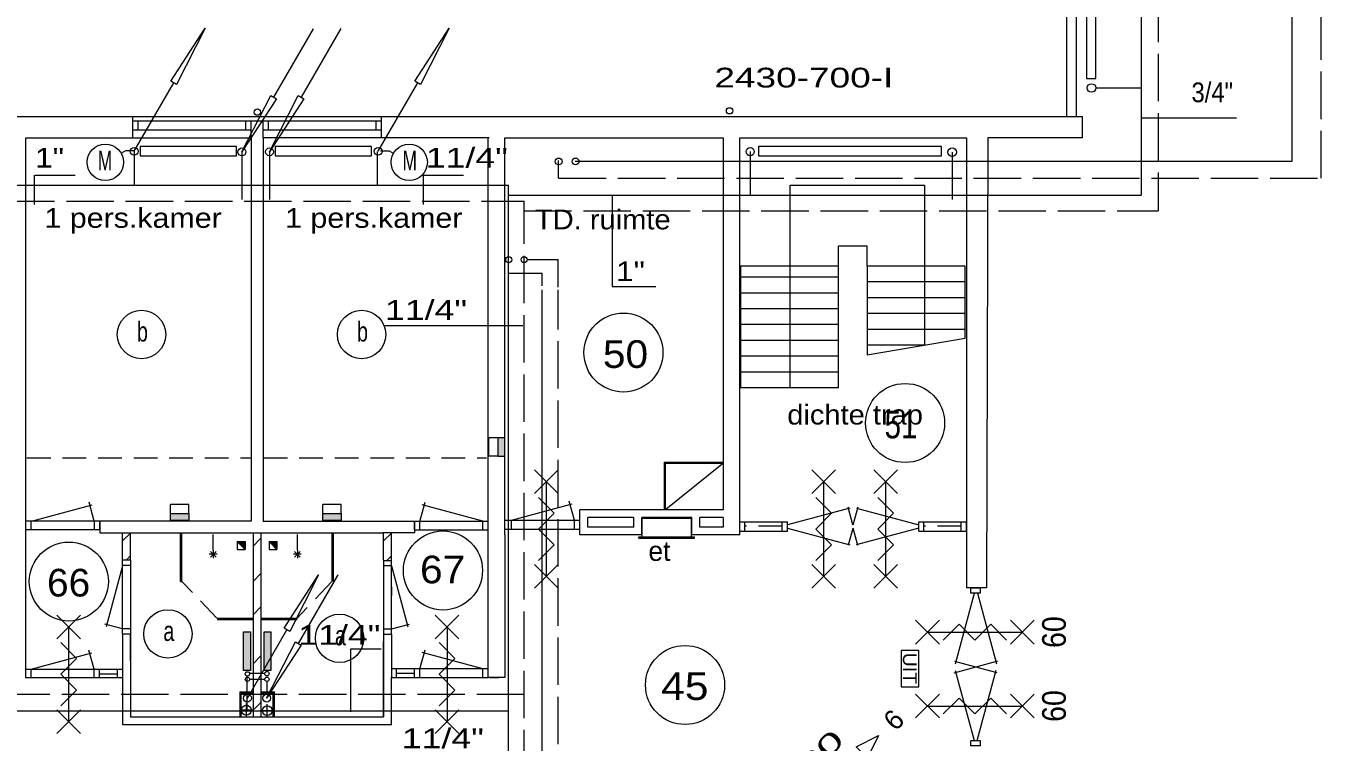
# Model space of a CAD drawing. Extents: x 295824 to 414724, y 24924 to 109024.
# Drawn here: x 320090 to 336476, y 39611 to 48675 of the extents above; entities that cross this region are included whole.
import ezdxf
from ezdxf.enums import TextEntityAlignment as Align

# ---------------------------------------------------------------- set-up
doc = ezdxf.new("R2010")
doc.units = 0
doc.header["$LTSCALE"] = 100
for name, pattern in [('DOT_DASHED', [7.7, 5, -1.2, 0.3, -1.2]), ('LONG_DASHED', [7.5, 6, -1.5]), ('MEDIUM_DASHED', [4.5, 3, -1.5])]:
    doc.linetypes.add(name, pattern=pattern)
doc.layers.add('16', color=7, linetype='Continuous', lineweight=13)
doc.layers.add('61', color=7, linetype='Continuous', lineweight=13)

msp = doc.modelspace()

# ---------------------------------------------------------------- hatches: boundary and pattern name
at = {"layer": '16'}
for points in [[(326148.9, 43232), (326148.9, 43463.5), (326062.4, 43463.5), (326062.4, 43232)], [(322152.7, 42415.9), (321921.2, 42415.9), (321921.2, 42502.4), (322152.7, 42502.4)], [(324077.6, 42415.9), (323846.1, 42415.9), (323846.1, 42502.4), (324077.6, 42502.4)], [(322843.9, 41008.8), (322929.4, 41008.8), (322929.4, 40516.6), (322843.9, 40516.6)], [(323103.1, 41008.8), (323188.5, 41008.8), (323188.5, 40516.6), (323103.1, 40516.6)]]:
    msp.add_hatch(color=256, dxfattribs=at).paths.add_polyline_path(points)
at = {"layer": '61'}
for points in [[(322863, 42048.6), (322763, 42148.6), (322863, 42148.6)], [(323266, 42048.6), (323166, 42148.6), (323266, 42148.6)]]:
    msp.add_hatch(color=256, dxfattribs=at).paths.add_polyline_path(points)

# ---------------------------------------------------------------- linework, layer by layer
at = {"layer": '16', "linetype": 'LONG_DASHED'}
for p, q in [((336475.7, 46746.4), (336475.7, 56755.7)), ((334414.3, 53571.2), (334414.3, 46333)), ((322820.3, 47078.4), (322820.3, 46458)), ((323173.8, 47078.1), (323173.8, 46458)), ((331809.5, 47078.1), (331809.5, 46333)), ((326829.9, 46746.4), (326829.9, 46969.9)), ((326829.9, 46746.4), (336475.7, 46746.4)), ((304851.7, 46458), (326394, 46458)), ((326394, 31665.3), (326394, 46458)), ((326394, 46333), (334414.3, 46333)), ((326435.5, 45718.9), (326822.5, 45718.9)), ((326822.5, 45368.8), (326822.5, 45718.9)), ((326822.5, 34334.7), (326822.5, 45336.6)), ((322919.9, 40407.1), (323111.4, 40407.1)), ((323142.4, 40217.7), (323142.4, 40381.3)), ((326394, 40214.6), (302769.9, 40214.6))]:
    msp.add_line(p, q, dxfattribs=at)
at = {"layer": '16'}
for p, q in [((336108.4, 46961.7), (336108.4, 56593.1)), ((334199, 51029.1), (334199, 46533)), ((323723, 48638.8), (323223, 47772.8)), ((324072.1, 48640.7), (323572.1, 47774.7)), ((321459.4, 47087.9), (321959.4, 47953.9)), ((324546.2, 47087.9), (325046.2, 47953.9)), ((333624, 47889.7), (334199, 47889.7)), ((334210.6, 47511.7), (335404.4, 47511.7)), ((321459.6, 47084.6), (321459.6, 46658)), ((324535.8, 47084.6), (324535.8, 46658)), ((329253.1, 47084.3), (329253.1, 46533)), ((327039.2, 46961.7), (336108.4, 46961.7)), ((320200.7, 46416.7), (320200.7, 46784.2)), ((320206.6, 46784.2), (320711.7, 46784.2)), ((303410.7, 46658), (326194, 46658)), ((309466.3, 46658), (325376.7, 46658)), ((326194, 31465.3), (326194, 46658)), ((326197.5, 46533), (334199, 46533)), ((326198.1, 45548.1), (326622.5, 45548.1)), ((326622.5, 45385.4), (326622.5, 45548.1)), ((326622.5, 34365.3), (326622.5, 45336.7)), ((326374.7, 44877.7), (324629.9, 44877.7)), ((326062.4, 43463.5), (325948.5, 43463.5)), ((321921.2, 42502.4), (321921.2, 42616.3)), ((323846.1, 42502.4), (323846.1, 42616.3)), ((324035.7, 41726.5), (323535.7, 40860.5)), ((322892.7, 40168.1), (323392.7, 41034.1)), ((323111.5, 40477.8), (322919.8, 40477.8)), ((322891.2, 40002.8), (322891.2, 40442.4)), ((326194, 40002.8), (302570.9, 40002.8))]:
    msp.add_line(p, q, dxfattribs=at)
for points in [[(333507, 50325.3), (333507, 48010.2), (333624.9, 48010.2), (333624.9, 50325.3)], [(322359.4, 48646.9), (321995.4, 47932.9), (321923.4, 47974.9)], [(325446.2, 48646.9), (325082.2, 47932.9), (325010.2, 47974.9)], [(322823, 47079.8), (323187, 47793.8), (323259, 47751.8)], [(323172.1, 47081.7), (323536.1, 47795.7), (323608.1, 47753.7)], [(321536.2, 47031.2), (322755.5, 47031.2), (322755.5, 47149.1), (321536.2, 47149.1)], [(323244.5, 47031.2), (324463.8, 47031.2), (324463.8, 47149.1), (323244.5, 47149.1)], [(329358.9, 47031.2), (331674, 47031.2), (331674, 47149.1), (329358.9, 47149.1)], [(326148.9, 43232), (326148.9, 43463.5), (326062.4, 43463.5), (326062.4, 43232)], [(322152.7, 42415.9), (321921.2, 42415.9), (321921.2, 42502.4), (322152.7, 42502.4)], [(324077.6, 42415.9), (323846.1, 42415.9), (323846.1, 42502.4), (324077.6, 42502.4)], [(323792.7, 41727.1), (323428.7, 41013.1), (323356.7, 41055.1)], [(322843.9, 41008.8), (322929.4, 41008.8), (322929.4, 40516.6), (322843.9, 40516.6)], [(323103.1, 41008.8), (323188.5, 41008.8), (323188.5, 40516.6), (323103.1, 40516.6)], [(323135.7, 40167.5), (323499.7, 40881.5), (323571.7, 40839.5)]]:
    msp.add_lwpolyline(points, close=True, dxfattribs=at)
for points in [[(321455.8, 47094.6), (321349.8, 47094.6), (321290.3, 47060.2)], [(324577.9, 47094.6), (324683.9, 47094.6), (324743.4, 47060.2)], [(325119.7, 46416.7), (325119.7, 46784.2), (325624.7, 46784.2)], [(327507.2, 46523.9), (327507.2, 45375.4), (328058.2, 45375.4)], [(326062.4, 43232), (325948.5, 43232), (325948.5, 43463.5)], [(322152.7, 42502.4), (322152.7, 42616.3), (321921.2, 42616.3)], [(324077.6, 42502.4), (324077.6, 42616.3), (323846.1, 42616.3)], [(324201.4, 39996.4), (324201.4, 40792.7), (324584, 40792.7)]]:
    msp.add_lwpolyline(points, dxfattribs=at)
for centre, radius in [((333569.6, 47889.7), 54.4), ((321094.7, 46949.2), 229.9), ((321459.4, 47087.6), 50), ((322823, 47080.2), 50), ((323172.1, 47082), 50), ((324546.2, 47087.6), 50), ((324939, 46949.2), 229.9), ((329253.1, 47084.3), 51.4), ((331809.5, 47078.1), 54.4), ((326829.9, 46960.4), 42.6), ((327044.2, 46960.4), 42.6), ((326197.9, 45716.6), 38), ((326393, 45716.6), 38), ((322892, 40474.8), 27.9), ((323139.4, 40477.8), 27.9), ((322892, 40407), 27.9), ((323139.4, 40407), 27.9), ((322892.7, 40167.8), 50), ((323135.7, 40167.8), 50)]:
    msp.add_circle(centre, radius, dxfattribs=at)
at = {"layer": '61'}
for p, q in [((333257, 47527.9), (333257, 54115.7)), ((333377, 54115.7), (333377, 47527.2)), ((301828.9, 47527.9), (333452, 47527.9)), ((313820.3, 47527.9), (333174.1, 47527.9)), ((321441.1, 47257.3), (321441.1, 47527.3)), ((324590.1, 47257.3), (324590.1, 47527.3)), ((333452, 47527.9), (333452, 47257.9)), ((321442, 47472.1), (322941, 47472.1)), ((321442, 47358.1), (321442, 47472.1)), ((321442, 47358.1), (322940, 47358.1)), ((321509, 47358.1), (321509, 47471.5)), ((322874, 47472.1), (324590, 47472.1)), ((322874, 47358.5), (322874, 47472.1)), ((322941, 47359.1), (322941, 47472.1)), ((322941.1, 47257.3), (322941.1, 47472.1)), ((323090.1, 47257.3), (323090.1, 47472.1)), ((323090.9, 47358.1), (323090.9, 47472.1)), ((323090.9, 47358.1), (324589, 47358.1)), ((323157.9, 47358.1), (323157.9, 47471.5)), ((324523, 47358.5), (324523, 47471.5)), ((324590, 47359.1), (324590, 47472.1)), ((320090.1, 47257.9), (322941.2, 47257.9)), ((320090.1, 40532.9), (320090.1, 47257.9)), ((320090.4, 47257.9), (322940.4, 47257.9)), ((320090.5, 47257.9), (322940.5, 47257.9)), ((322940.1, 47257.9), (322940.1, 42407.9)), ((325940.1, 47257.9), (323090.1, 47257.9)), ((325949, 47257.9), (323099, 47257.9)), ((325940.1, 40428.5), (325940.1, 47257.9)), ((328910.1, 47257.9), (328910.1, 42552.9)), ((332260.1, 47257.9), (332241.7, 41563.5)), ((333452, 47257.9), (332260.1, 47257.9)), ((330368.9, 45635), (330368.9, 45892.9)), ((330368.9, 45892.9), (330732.6, 45892.9)), ((330732.6, 45635), (330732.6, 45892.9)), ((331972.5, 45635), (330732.6, 45635)), ((331972.5, 44722.2), (331972.5, 45635)), ((329129, 45498.6), (330368.9, 45498.6)), ((331972.5, 45435), (330732.6, 45435)), ((329129, 45298.6), (330368.9, 45298.6)), ((331972.5, 45235), (330732.6, 45235)), ((329129, 45098.6), (330368.9, 45098.6)), ((329129, 44898.6), (330368.9, 44898.6)), ((331972.5, 45035), (330732.6, 45035)), ((331972.5, 44835), (330732.6, 44835)), ((329129, 44698.6), (330368.9, 44698.6)), ((330732.6, 44511), (331972.5, 44722.2)), ((331460.5, 44635), (330732.6, 44635)), ((329129, 44498.6), (330368.9, 44498.6)), ((329129, 44298.6), (330368.9, 44298.6)), ((329129, 44098.6), (330368.9, 44098.6)), ((328168.4, 43154.8), (328910.1, 43154.8)), ((328168.4, 42552.9), (328168.4, 43154.8)), ((328183.4, 43139.8), (328910.1, 43139.8)), ((328183.4, 42552.9), (328183.4, 43139.8)), ((328898.2, 43126.8), (328183.9, 42555.9)), ((326523.6, 42757.7), (326823.6, 43057.7)), ((326823.6, 42757.7), (326523.6, 43057.7)), ((330031.9, 42757.7), (330331.9, 43057.7)), ((330331.9, 42757.7), (330031.9, 43057.7)), ((330816, 42757.7), (331116, 43057.7)), ((331116, 42757.7), (330816, 43057.7)), ((326673.6, 42907.7), (326673.6, 41707.7)), ((330181.9, 42907.7), (330181.9, 41707.7)), ((330966, 42907.7), (330966, 41707.7)), ((320158.9, 42409.2), (320926.2, 42614.8)), ((320953.4, 42407.1), (320888.4, 42649.8)), ((325075.2, 42405.1), (325140.3, 42647.8)), ((325869.8, 42407.2), (325102.5, 42612.8)), ((326234.9, 42421.6), (327002.2, 42627.2)), ((327029.5, 42419.5), (326964.4, 42662.2)), ((327099.3, 42232.9), (327099.3, 42552.9)), ((328910.1, 42552.9), (327099.3, 42552.9)), ((327780.3, 42452.9), (327199.3, 42452.9)), ((327780.3, 42332.9), (327780.3, 42452.9)), ((327880.3, 42234.5), (327880.3, 42452.9)), ((328515.5, 42452.9), (327880.3, 42452.9)), ((327884.6, 42217.1), (327884.6, 42444.5)), ((327884.6, 42444.5), (328508.9, 42444.5)), ((328508.9, 42209.4), (328508.9, 42444.5)), ((328910.1, 42552.9), (328512.1, 42552.9)), ((328515.5, 42232.9), (328515.5, 42452.9)), ((328910.1, 42452.9), (328615.5, 42452.9)), ((328910.1, 42452.9), (328910.1, 42332.9)), ((330512, 42572.2), (329725.6, 42361.4)), ((330553, 42361.5), (330493.5, 42583.4)), ((330556, 42361.1), (330617.3, 42590)), ((330597.9, 42572.2), (331385.2, 42361.3)), ((321021.2, 42299.4), (320090.4, 42299.4)), ((320156.3, 42299.1), (320156.3, 42409.1)), ((322940.1, 42407.9), (320878.9, 42407.9)), ((320956.3, 42299.1), (320956.3, 42409.1)), ((321023.3, 42299.1), (321023.3, 42409.1)), ((323088.9, 42407.9), (325031.4, 42407.9)), ((323090.4, 42407.9), (325938.2, 42407.9)), ((325005.4, 42297.1), (325005.4, 42407.1)), ((325007.5, 42297.4), (325938.3, 42297.4)), ((325072.4, 42297.1), (325072.4, 42407.1)), ((325872.4, 42297.1), (325872.4, 42407.1)), ((325938.3, 42297.4), (325938.3, 42407.8)), ((326152.8, 42421), (327089.5, 42421)), ((326152.8, 42307.3), (327093.8, 42307.3)), ((326232.3, 42311.5), (326232.3, 42421.5)), ((327032.3, 42311.5), (327032.3, 42421.5)), ((329120, 42398.2), (329724.8, 42398.2)), ((329120, 42282), (329120, 42396)), ((329120.6, 42282), (329724.8, 42282)), ((329187, 42282.9), (329187, 42396.9)), ((329657.8, 42282.9), (329657.8, 42396.9)), ((329724.8, 42282), (329724.8, 42398.2)), ((329724.9, 42319), (330514.2, 42107.5)), ((330497.1, 42106.1), (330554, 42318.6)), ((330615.2, 42097.9), (330555.9, 42319.3)), ((331385, 42319.1), (330593.9, 42107.1)), ((331384.8, 42282), (331384.8, 42398.2)), ((331384.8, 42398.2), (331990, 42398.2)), ((331384.8, 42282), (331989.4, 42282)), ((331451.8, 42282.9), (331451.8, 42396.9)), ((331923, 42281.8), (331923, 42394.9)), ((331990, 42280.9), (331990, 42394.9)), ((321024.2, 42257.9), (324614.3, 42257.9)), ((321314, 41911.5), (321314, 42257.9)), ((321314, 42157.2), (321414.4, 42257.6)), ((321412.7, 41911.5), (321412.7, 42257.9)), ((322046.7, 41644.6), (322046.7, 42253)), ((322064.7, 41644.6), (322064.7, 42253)), ((322459.5, 42039.2), (322459.5, 42239.2)), ((322963.9, 42257.9), (322963.9, 39932.9)), ((322964.4, 42093), (323062.9, 42191.5)), ((323063.9, 42257.9), (323063.9, 39932.9)), ((323524, 42039.2), (323524, 42239.2)), ((323964.5, 41650.7), (323964.5, 42255.5)), ((323982.5, 41650.7), (323982.5, 42255.5)), ((324614.3, 41911.9), (324614.3, 42258.3)), ((324614.5, 42157.2), (324714.9, 42257.6)), ((324714.1, 41911.5), (324714.1, 42257.9)), ((327880.3, 42232.9), (327099.3, 42232.9)), ((327845.3, 42209.4), (328546.5, 42209.4)), ((327845.3, 42191.9), (327845.3, 42209.4)), ((327845.3, 42191.9), (328546.5, 42191.9)), ((329120.1, 42232.9), (328515.5, 42232.9)), ((328546.5, 42191.9), (328546.5, 42209.4)), ((321356.4, 41913.2), (321413, 41969.9)), ((322509.5, 41989.2), (322409.5, 41989.2)), ((322494.9, 42024.5), (322424.2, 41953.8)), ((322494.9, 41953.8), (322424.2, 42024.5)), ((322459.5, 42039.2), (322459.5, 41939.2)), ((323574, 41989.2), (323474, 41989.2)), ((323559.4, 42024.5), (323488.7, 41953.8)), ((323559.4, 41953.8), (323488.7, 42024.5)), ((323524, 42039.2), (323524, 41939.2)), ((324658.3, 41913.2), (324714.9, 41969.9)), ((321314, 41841.3), (321107.1, 41069.1)), ((321313.8, 40977.9), (321313.8, 41911.9)), ((321413.8, 41911.9), (321313.8, 41911.9)), ((321413.9, 41844.9), (321313.8, 41844.9)), ((321413.8, 41911.9), (321413.8, 40977.9)), ((324613.7, 41844.5), (324713.9, 41844.5)), ((324613.9, 41911.5), (324613.9, 40977.5)), ((324614.3, 41911.5), (324714.5, 41911.5)), ((324713.6, 41841), (324920.5, 41068.7)), ((324713.9, 40976.7), (324713.9, 41911.5)), ((326523.6, 41557.7), (326823.6, 41857.7)), ((326823.6, 41557.7), (326523.6, 41857.7)), ((330031.9, 41557.7), (330331.9, 41857.7)), ((330331.9, 41557.7), (330031.9, 41857.7)), ((330816, 41557.7), (331116, 41857.7)), ((331116, 41557.7), (330816, 41857.7)), ((322046.7, 41644.6), (322064.7, 41644.6)), ((322964.4, 41645.4), (323062.9, 41743.9)), ((323964.5, 41650.7), (323982.5, 41650.7)), ((324714, 41578.4), (324714, 41468)), ((331851.1, 40602.2), (332090.7, 41496.3)), ((332241.7, 41563.5), (331990.1, 41563.5)), ((332130.7, 41496.3), (332369.8, 40603.9)), ((322964.4, 41222.9), (323062.9, 41321.4)), ((320480.8, 40919.8), (320780.8, 41219.8)), ((320780.8, 40919.8), (320480.8, 41219.8)), ((322963.5, 41158.7), (322513.2, 41158.7)), ((323514.9, 41176.7), (323064.9, 41176.7)), ((323514.9, 41158.7), (323064.9, 41158.7)), ((323514.9, 41176.7), (323514.9, 41158.7)), ((325268.5, 40919.8), (325568.5, 41219.8)), ((325568.5, 40919.8), (325268.5, 41219.8)), ((331646.2, 40852.6), (331346.2, 41152.6)), ((331646.2, 41152.6), (331346.2, 40852.6)), ((332846.2, 40852.6), (332546.2, 41152.6)), ((332846.2, 41152.6), (332546.2, 40852.6)), ((320630.8, 41069.8), (320630.8, 39869.8)), ((321314, 41043.9), (321086.7, 41104.8)), ((321413.8, 40977.9), (321313.8, 40977.9)), ((321313.9, 40975.3), (321313.9, 40188.2)), ((321413.6, 41044.9), (321314.3, 41044.9)), ((321413.9, 40638.2), (321413.9, 40975.3)), ((324613.9, 40977.5), (324613.9, 39932.9)), ((324613.9, 40977.5), (324713.9, 40977.5)), ((324614, 41044.5), (324713.4, 41044.5)), ((324713.6, 41043.5), (324940.9, 41104.4)), ((324713.9, 40977.5), (324713.9, 40532.9)), ((325418.5, 41069.8), (325418.5, 39869.8)), ((331496.2, 41002.6), (332696.2, 41002.6)), ((320157.7, 40535.1), (320924.9, 40740.7)), ((320952.2, 40532.9), (320887.2, 40775.7)), ((322964.4, 40603), (323062.9, 40701.4)), ((325075.2, 40536.8), (325140.3, 40779.5)), ((325869.8, 40539), (325102.5, 40744.6)), ((320155.1, 40424.9), (320155.1, 40534.9)), ((320955.1, 40424.9), (320955.1, 40534.9)), ((321022.1, 40424.9), (321022.1, 40534.9)), ((321022.9, 40475.7), (321247.6, 40475.7)), ((321247.6, 40424.9), (321247.6, 40534.9)), ((324779.9, 40428.8), (324779.9, 40538.8)), ((325004.6, 40479.6), (324779.9, 40479.6)), ((325005.4, 40428.8), (325005.4, 40538.8)), ((325072.4, 40428.8), (325072.4, 40538.8)), ((325872.4, 40428.8), (325872.4, 40538.8)), ((332107.3, 40560.2), (331828.5, 40485.5)), ((332106.9, 40561.2), (331843.4, 40631.8)), ((331847.3, 40516.5), (332084.6, 39630.7)), ((332382.4, 40635.1), (332108.4, 40561.7)), ((332376.5, 40488.2), (332109.1, 40559.9)), ((332124.6, 39630.6), (332363.2, 40520.9)), ((325959.8, 40428.6), (326073.8, 40428.6)), ((322796.2, 40248), (322963.9, 40248)), ((322796.2, 40248), (322796.2, 39932.9)), ((322810.5, 40234.4), (322963.9, 40234.4)), ((322810.5, 40234.4), (322810.5, 39934)), ((323064, 40234.4), (323218.7, 40234.4)), ((323065, 40248), (323233.7, 40248)), ((323218.7, 39932.9), (323218.7, 40234.4)), ((323233.7, 39932.9), (323233.7, 40248)), ((331646.2, 39917.2), (331346.2, 40217.2)), ((331646.2, 40217.2), (331346.2, 39917.2)), ((332846.2, 39917.2), (332546.2, 40217.2)), ((332846.2, 40217.2), (332546.2, 39917.2)), ((320480.8, 39719.8), (320780.8, 40019.8)), ((320780.8, 39719.8), (320480.8, 40019.8)), ((322977.5, 40026.8), (323062.9, 40112.1)), ((325268.5, 39719.8), (325568.5, 40019.8)), ((325568.5, 39719.8), (325268.5, 40019.8)), ((331496.2, 40067.2), (332696.2, 40067.2))]:
    msp.add_line(p, q, dxfattribs=at)
at = {"layer": '61', "linetype": 'MEDIUM_DASHED'}
for p, q in [((320103.3, 43208.1), (322935.1, 43208.1)), ((323098.4, 43208.1), (325916.3, 43208.1)), ((329656.2, 42342.2), (329186.7, 42342.2)), ((331921.7, 42342.2), (331452.9, 42342.2)), ((322505.8, 41179.8), (322064, 41644.8)), ((323960.1, 41643.1), (323516.1, 41175.8))]:
    msp.add_line(p, q, dxfattribs=at)
at = {"layer": '61', "linetype": 'DOT_DASHED'}
for p, q in [((322968, 40015.2), (322804, 40015.2)), ((322879.5, 39934.8), (322879.5, 40098.9)), ((323227.8, 40007.7), (323063.7, 40007.7)), ((323142.7, 39933.5), (323142.7, 40092.8))]:
    msp.add_line(p, q, dxfattribs=at)
at = {"layer": '61'}
for points in [[(325940.4, 47257.9), (323090.4, 47257.9), (323090.4, 42407.9)], [(325940.5, 47257.9), (323090.5, 47257.9), (323090.5, 42407.9)], [(326150.1, 42234.5), (326150.1, 47257.9), (328910.1, 47257.9)], [(329120.1, 42232.9), (329120.1, 47257.9), (331990.1, 47257.9), (331990.1, 41563.5)], [(329757.2, 44098.6), (329757.2, 46659.3), (331460, 46659.3), (331460, 44634.9)], [(331972.5, 45635), (330732.6, 45635), (330732.6, 44511)], [(326573.6, 42707.7), (326773.6, 42507.7), (326573.6, 42307.7), (326773.6, 42107.7), (326573.6, 41907.7)], [(330081.9, 42707.7), (330281.9, 42507.7), (330081.9, 42307.7), (330281.9, 42107.7), (330081.9, 41907.7)], [(330866, 42707.7), (331066, 42507.7), (330866, 42307.7), (331066, 42107.7), (330866, 41907.7)], [(327780.3, 42332.9), (327199.3, 42332.9), (327199.3, 42452.9)], [(328910.1, 42332.9), (328615.5, 42332.9), (328615.5, 42452.9)], [(320090.4, 42299.4), (320090.4, 42409.8), (321023.7, 42409.8)], [(322938.9, 42407.9), (321024.2, 42407.9), (321024.2, 42257.9)], [(325005, 42407.8), (325005, 42257.9), (324599.6, 42257.9)], [(322763, 42148.6), (322863, 42148.6), (322863, 42048.6)], [(323166, 42148.6), (323266, 42148.6), (323266, 42048.6)], [(326150.1, 42232.9), (326150.1, 40428.5), (325940.1, 40428.5)], [(321413.9, 41158.7), (321413.9, 39932.9), (323293.9, 39932.9)], [(322963.5, 41176.7), (322513.2, 41176.7), (322513.2, 41158.7)], [(331696.2, 40902.6), (331896.2, 41102.6), (332096.2, 40902.6), (332296.2, 41102.6), (332496.2, 40902.6)], [(320530.8, 40869.8), (320730.8, 40669.8), (320530.8, 40469.8), (320730.8, 40269.8), (320530.8, 40069.8)], [(323088.7, 39932.9), (324613.9, 39932.9), (324613.9, 40882.9)], [(325318.5, 40869.8), (325518.5, 40669.8), (325318.5, 40469.8), (325518.5, 40269.8), (325318.5, 40069.8)], [(321313.9, 40432.9), (321313.9, 39832.9), (324713.9, 39832.9), (324713.9, 40432.9)], [(331696.2, 39967.2), (331896.2, 40167.2), (332096.2, 39967.2), (332296.2, 40167.2), (332496.2, 39967.2)]]:
    msp.add_lwpolyline(points, dxfattribs=at)
for points in [[(330368.9, 45635), (329129, 45635), (329129, 44098.6), (330368.9, 44098.6)], [(322763, 42148.6), (322763, 42048.6), (322863, 42048.6)], [(322863, 42048.6), (322763, 42148.6), (322863, 42148.6)], [(323166, 42148.6), (323166, 42048.6), (323266, 42048.6)], [(323266, 42048.6), (323166, 42148.6), (323266, 42148.6)], [(332046.2, 41496.3), (332046.2, 41563.3), (332162.4, 41563.3), (332162.4, 41496.3)], [(331163.5, 40768.9), (331163.5, 40309.3), (331388.1, 40309.3), (331388.1, 40768.9)], [(320089.2, 40425.3), (320089.2, 40535.6), (321313.5, 40535.6), (321313.5, 40425.3)], [(325938.3, 40429.1), (325938.3, 40539.5), (324714, 40539.5), (324714, 40429.1)], [(330735.4, 39411.2), (330594, 39552.7), (330876.8, 39694.1)], [(332046.2, 39563.6), (332046.2, 39630.6), (332162.4, 39630.6), (332162.4, 39563.6)]]:
    msp.add_lwpolyline(points, close=True, dxfattribs=at)
for centre, radius in [((323018.5, 47584.2), 40), ((328991.8, 47600.4), 40), ((321552.2, 44769.7), 306.3), ((324336.3, 44769.7), 306.3), ((327649.2, 44541.3), 500), ((331212.8, 43649.8), 500), ((325366.2, 41783), 500), ((320633.2, 41643.7), 500), ((321886.3, 40980.6), 306.3), ((324057.9, 40924.8), 306.3), ((328428.7, 40334.2), 500), ((322879.5, 40015.2), 62.5), ((323143.3, 40008.4), 62.5)]:
    msp.add_circle(centre, radius, dxfattribs=at)

# ---------------------------------------------------------------- texts
at = {"layer": '16'}
for s, width, p in [('2430-700-I', 1.4, (328800.1, 47895.8)), ('3/4"', 0.9, (334836.2, 47709.2)), ('1"', 1.2, (320206.1, 46881.6)), ('M', 0.65, (321000.7, 46846.2)), ('M', 0.65, (324855.9, 46846.2)), ('11/4"', 1.35, (325148.6, 46881.6)), ('1"', 1.2, (327555.6, 45445.1)), ('11/4"', 1.35, (324632.4, 44955)), (' 11/4"', 1.35, (323410.9, 40842.9)), (' 11/4"', 1.35, (324719.8, 39533.9))]:
    msp.add_text(s, height=250, dxfattribs=dict(at, width=width)).set_placement(p)
at = {"layer": '61'}
for s, height, width, p in [('1 pers.kamer', 250, 1.15, (320324.6, 46120.2)), ('1 pers.kamer', 250, 1.15, (323369, 46120.2)), ('TD. ruimte', 250, 1.1, (326530.2, 46100.3)), ('b', 250, 0.75, (321494.2, 44680.6)), ('b', 250, 0.75, (324278.3, 44680.6)), ('50', 350, 1.1, (327389.2, 44346.9)), ('dichte trap', 250, 1.1, (329721.9, 43630.2)), ('51', 350, 0.8, (330952.9, 43455.3)), ('a', 250, 0.75, (321828.3, 40891.4)), ('a', 250, 0.75, (323999.9, 40835.7))]:
    msp.add_text(s, height=height, dxfattribs=dict(at, width=width)).set_placement(p)
msp.add_text('et', height=250, dxfattribs=at).set_placement((327965.5, 41904.5))
for s, width, p in [('67', 1.1, (325361.9, 41621)), ('66', 1.05, (320630.3, 41453.9)), ('45', 1.15, (328425.8, 40144.4))]:
    msp.add_text(s, height=350, dxfattribs=dict(at, width=width)).set_placement(p, align=Align.CENTER)
at = {"layer": '61', "width": 0.9}
for p in [(333246.2, 41003.4), (333246.2, 40068)]:
    msp.add_text('60', height=300, rotation=90, dxfattribs=at).set_placement(p, align=Align.CENTER)
at = {"layer": '61'}
for s, height, rotation, width, p in [('UIT', 175, 270, 1.05, (331184.9, 40742.2)), ('20', 250, 45, 1.75, (330001.4, 39156))]:
    msp.add_text(s, height=height, rotation=rotation, dxfattribs=dict(at, width=width)).set_placement(p)
msp.add_text('6', height=250, rotation=45, dxfattribs=at).set_placement((331091.3, 39739.9))

doc.saveas('drawing.dxf')
